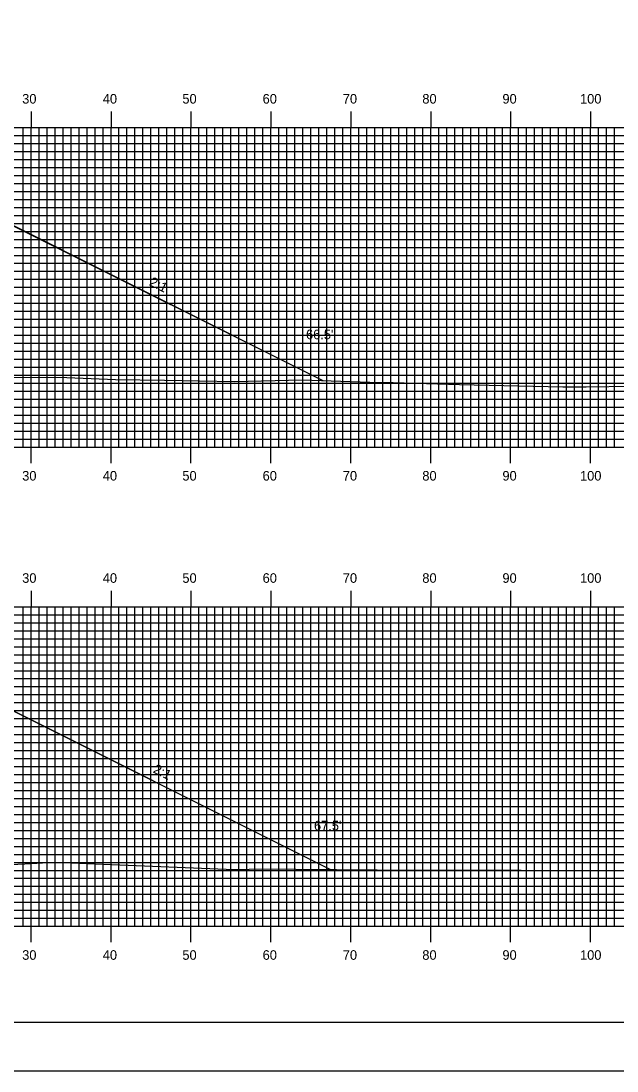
# Model space of a CAD drawing. Extents: x 1810587 to 1810930, y 442591 to 442811.
# Drawn here: x 1810781.1 to 1810855.7, y 442590.5 to 442722 of the extents above; entities that cross this region are included whole.
import ezdxf

# ---------------------------------------------------------------- set-up
doc = ezdxf.new("R2010")
doc.units = 0
for name, color, linetype in [('ANNOTATION', 7, 'Continuous'), ('BORDER', 7, 'Continuous'), ('D_Roadway_Centerline', 7, 'Continuous'), ('D_Roadway_SlopeLines', 7, 'Continuous'), ('D_Text_Standard', 7, 'Continuous'), ('H_V ANNOTATION', 7, 'Continuous'), ('MAJOR', 7, 'Continuous'), ('MINOR', 7, 'Continuous'), ('PLOT BOUNDARY', 7, 'Continuous'), ('S_Roadway_Centerline', 7, 'Continuous')]:
    doc.layers.add(name, color=color, linetype=linetype)

msp = doc.modelspace()

# ---------------------------------------------------------------- linework, layer by layer
at = {"layer": 'BORDER'}
msp.add_lwpolyline([(1810602.78, 442596.67), (1810922.78, 442596.67), (1810922.78, 442806.67), (1810602.78, 442806.67)], close=True, dxfattribs=at)
at = {"layer": 'D_Roadway_Centerline'}
for points in [[(1810685.73, 442678.41), (1810724.17, 442697.62), (1810729.38, 442700.23), (1810732.38, 442700.29), (1810740.38, 442700.45), (1810752.38, 442699.87), (1810764.38, 442699.29), (1810772.38, 442698.91), (1810775.38, 442698.77), (1810780.91, 442696), (1810818.89, 442677.01)], [(1810686.18, 442617.88), (1810724.17, 442636.87), (1810729.38, 442639.48), (1810732.38, 442639.54), (1810740.38, 442639.7), (1810752.38, 442639.12), (1810764.38, 442638.54), (1810772.38, 442638.16), (1810775.38, 442638.02), (1810780.91, 442635.25), (1810819.86, 442615.77)]]:
    msp.add_lwpolyline(points, dxfattribs=at)
at = {"layer": 'D_Roadway_SlopeLines'}
for points in [[(1810775.38, 442698.77), (1810818.89, 442677.01)], [(1810775.38, 442638.02), (1810819.86, 442615.77)]]:
    msp.add_lwpolyline(points, dxfattribs=at)
at = {"layer": 'MAJOR'}
for p, q in [((1810782.38, 442710.67), (1810782.38, 442708.67)), ((1810792.38, 442710.67), (1810792.38, 442708.67)), ((1810802.38, 442710.67), (1810802.38, 442708.67)), ((1810812.38, 442710.67), (1810812.38, 442708.67)), ((1810822.38, 442710.67), (1810822.38, 442708.67)), ((1810832.38, 442710.67), (1810832.38, 442708.67)), ((1810842.38, 442710.67), (1810842.38, 442708.67)), ((1810852.38, 442710.67), (1810852.38, 442708.67)), ((1810612.38, 442708.67), (1810892.38, 442708.67)), ((1810612.38, 442708.67), (1810892.38, 442708.67)), ((1810782.38, 442668.67), (1810782.38, 442708.67)), ((1810792.38, 442668.67), (1810792.38, 442708.67)), ((1810802.38, 442668.67), (1810802.38, 442708.67)), ((1810812.38, 442668.67), (1810812.38, 442708.67)), ((1810822.38, 442668.67), (1810822.38, 442708.67)), ((1810832.38, 442668.67), (1810832.38, 442708.67)), ((1810842.38, 442668.67), (1810842.38, 442708.67)), ((1810852.38, 442668.67), (1810852.38, 442708.67)), ((1810612.38, 442703.67), (1810892.38, 442703.67)), ((1810612.38, 442698.67), (1810892.38, 442698.67)), ((1810612.38, 442693.67), (1810892.38, 442693.67)), ((1810612.38, 442688.67), (1810892.38, 442688.67)), ((1810612.38, 442683.67), (1810892.38, 442683.67)), ((1810612.38, 442678.67), (1810892.38, 442678.67)), ((1810612.38, 442673.67), (1810892.38, 442673.67)), ((1810612.38, 442668.67), (1810892.38, 442668.67)), ((1810612.38, 442668.67), (1810892.38, 442668.67)), ((1810782.38, 442666.66), (1810782.38, 442668.67)), ((1810792.38, 442666.66), (1810792.38, 442668.67)), ((1810802.38, 442666.66), (1810802.38, 442668.67)), ((1810812.38, 442666.66), (1810812.38, 442668.67)), ((1810822.38, 442666.66), (1810822.38, 442668.67)), ((1810832.38, 442666.66), (1810832.38, 442668.67)), ((1810842.38, 442666.66), (1810842.38, 442668.67)), ((1810852.38, 442666.66), (1810852.38, 442668.67)), ((1810782.38, 442650.67), (1810782.38, 442648.67)), ((1810792.38, 442650.67), (1810792.38, 442648.67)), ((1810802.38, 442650.67), (1810802.38, 442648.67)), ((1810812.38, 442650.67), (1810812.38, 442648.67)), ((1810822.38, 442650.67), (1810822.38, 442648.67)), ((1810832.38, 442650.67), (1810832.38, 442648.67)), ((1810842.38, 442650.67), (1810842.38, 442648.67)), ((1810852.38, 442650.67), (1810852.38, 442648.67)), ((1810612.38, 442648.67), (1810892.38, 442648.67)), ((1810612.38, 442648.67), (1810892.38, 442648.67)), ((1810782.38, 442608.67), (1810782.38, 442648.67)), ((1810792.38, 442608.67), (1810792.38, 442648.67)), ((1810802.38, 442608.67), (1810802.38, 442648.67)), ((1810812.38, 442608.67), (1810812.38, 442648.67)), ((1810822.38, 442608.67), (1810822.38, 442648.67)), ((1810832.38, 442608.67), (1810832.38, 442648.67)), ((1810842.38, 442608.67), (1810842.38, 442648.67)), ((1810852.38, 442608.67), (1810852.38, 442648.67)), ((1810612.38, 442643.67), (1810892.38, 442643.67)), ((1810612.38, 442638.67), (1810892.38, 442638.67)), ((1810612.38, 442633.67), (1810892.38, 442633.67)), ((1810612.38, 442628.67), (1810892.38, 442628.67)), ((1810612.38, 442623.67), (1810892.38, 442623.67)), ((1810612.38, 442618.67), (1810892.38, 442618.67)), ((1810612.38, 442613.67), (1810892.38, 442613.67)), ((1810612.38, 442608.67), (1810892.38, 442608.67)), ((1810612.38, 442608.67), (1810892.38, 442608.67)), ((1810782.38, 442606.66), (1810782.38, 442608.67)), ((1810792.38, 442606.66), (1810792.38, 442608.67)), ((1810802.38, 442606.66), (1810802.38, 442608.67)), ((1810812.38, 442606.66), (1810812.38, 442608.67)), ((1810822.38, 442606.66), (1810822.38, 442608.67)), ((1810832.38, 442606.66), (1810832.38, 442608.67)), ((1810842.38, 442606.66), (1810842.38, 442608.67)), ((1810852.38, 442606.66), (1810852.38, 442608.67))]:
    msp.add_line(p, q, dxfattribs=at)
at = {"layer": 'MINOR'}
for p, q in [((1810781.38, 442668.67), (1810781.38, 442708.67)), ((1810783.38, 442668.67), (1810783.38, 442708.67)), ((1810784.38, 442668.67), (1810784.38, 442708.67)), ((1810785.38, 442668.67), (1810785.38, 442708.67)), ((1810786.38, 442668.67), (1810786.38, 442708.67)), ((1810787.38, 442668.67), (1810787.38, 442708.67)), ((1810788.38, 442668.67), (1810788.38, 442708.67)), ((1810789.38, 442668.67), (1810789.38, 442708.67)), ((1810790.38, 442668.67), (1810790.38, 442708.67)), ((1810791.38, 442668.67), (1810791.38, 442708.67)), ((1810793.38, 442668.67), (1810793.38, 442708.67)), ((1810794.38, 442668.67), (1810794.38, 442708.67)), ((1810795.38, 442668.67), (1810795.38, 442708.67)), ((1810796.38, 442668.67), (1810796.38, 442708.67)), ((1810797.38, 442668.67), (1810797.38, 442708.67)), ((1810798.38, 442668.67), (1810798.38, 442708.67)), ((1810799.38, 442668.67), (1810799.38, 442708.67)), ((1810800.38, 442668.67), (1810800.38, 442708.67)), ((1810801.38, 442668.67), (1810801.38, 442708.67)), ((1810803.38, 442668.67), (1810803.38, 442708.67)), ((1810804.38, 442668.67), (1810804.38, 442708.67)), ((1810805.38, 442668.67), (1810805.38, 442708.67)), ((1810806.38, 442668.67), (1810806.38, 442708.67)), ((1810807.38, 442668.67), (1810807.38, 442708.67)), ((1810808.38, 442668.67), (1810808.38, 442708.67)), ((1810809.38, 442668.67), (1810809.38, 442708.67)), ((1810810.38, 442668.67), (1810810.38, 442708.67)), ((1810811.38, 442668.67), (1810811.38, 442708.67)), ((1810813.38, 442668.67), (1810813.38, 442708.67)), ((1810814.38, 442668.67), (1810814.38, 442708.67)), ((1810815.38, 442668.67), (1810815.38, 442708.67)), ((1810816.38, 442668.67), (1810816.38, 442708.67)), ((1810817.38, 442668.67), (1810817.38, 442708.67)), ((1810818.38, 442668.67), (1810818.38, 442708.67)), ((1810819.38, 442668.67), (1810819.38, 442708.67)), ((1810820.38, 442668.67), (1810820.38, 442708.67)), ((1810821.38, 442668.67), (1810821.38, 442708.67)), ((1810823.38, 442668.67), (1810823.38, 442708.67)), ((1810824.38, 442668.67), (1810824.38, 442708.67)), ((1810825.38, 442668.67), (1810825.38, 442708.67)), ((1810826.38, 442668.67), (1810826.38, 442708.67)), ((1810827.38, 442668.67), (1810827.38, 442708.67)), ((1810828.38, 442668.67), (1810828.38, 442708.67)), ((1810829.38, 442668.67), (1810829.38, 442708.67)), ((1810830.38, 442668.67), (1810830.38, 442708.67)), ((1810831.38, 442668.67), (1810831.38, 442708.67)), ((1810833.38, 442668.67), (1810833.38, 442708.67)), ((1810834.38, 442668.67), (1810834.38, 442708.67)), ((1810835.38, 442668.67), (1810835.38, 442708.67)), ((1810836.38, 442668.67), (1810836.38, 442708.67)), ((1810837.38, 442668.67), (1810837.38, 442708.67)), ((1810838.38, 442668.67), (1810838.38, 442708.67)), ((1810839.38, 442668.67), (1810839.38, 442708.67)), ((1810840.38, 442668.67), (1810840.38, 442708.67)), ((1810841.38, 442668.67), (1810841.38, 442708.67)), ((1810843.38, 442668.67), (1810843.38, 442708.67)), ((1810844.38, 442668.67), (1810844.38, 442708.67)), ((1810845.38, 442668.67), (1810845.38, 442708.67)), ((1810846.38, 442668.67), (1810846.38, 442708.67)), ((1810847.38, 442668.67), (1810847.38, 442708.67)), ((1810848.38, 442668.67), (1810848.38, 442708.67)), ((1810849.38, 442668.67), (1810849.38, 442708.67)), ((1810850.38, 442668.67), (1810850.38, 442708.67)), ((1810851.38, 442668.67), (1810851.38, 442708.67)), ((1810853.38, 442668.67), (1810853.38, 442708.67)), ((1810854.38, 442668.67), (1810854.38, 442708.67)), ((1810855.38, 442668.67), (1810855.38, 442708.67)), ((1810612.38, 442707.67), (1810892.38, 442707.67)), ((1810612.38, 442706.67), (1810892.38, 442706.67)), ((1810612.38, 442705.67), (1810892.38, 442705.67)), ((1810612.38, 442704.67), (1810892.38, 442704.67)), ((1810612.38, 442702.67), (1810892.38, 442702.67)), ((1810612.38, 442701.67), (1810892.38, 442701.67)), ((1810612.38, 442700.67), (1810892.38, 442700.67)), ((1810612.38, 442699.67), (1810892.38, 442699.67)), ((1810612.38, 442697.67), (1810892.38, 442697.67)), ((1810612.38, 442696.67), (1810892.38, 442696.67)), ((1810612.38, 442695.67), (1810892.38, 442695.67)), ((1810612.38, 442694.67), (1810892.38, 442694.67)), ((1810612.38, 442692.67), (1810892.38, 442692.67)), ((1810612.38, 442691.67), (1810892.38, 442691.67)), ((1810612.38, 442690.67), (1810892.38, 442690.67)), ((1810612.38, 442689.67), (1810892.38, 442689.67)), ((1810612.38, 442687.67), (1810892.38, 442687.67)), ((1810612.38, 442686.67), (1810892.38, 442686.67)), ((1810612.38, 442685.67), (1810892.38, 442685.67)), ((1810612.38, 442684.67), (1810892.38, 442684.67)), ((1810612.38, 442682.67), (1810892.38, 442682.67)), ((1810612.38, 442681.67), (1810892.38, 442681.67)), ((1810612.38, 442680.67), (1810892.38, 442680.67)), ((1810612.38, 442679.67), (1810892.38, 442679.67)), ((1810612.38, 442677.67), (1810892.38, 442677.67)), ((1810612.38, 442676.67), (1810892.38, 442676.67)), ((1810612.38, 442675.67), (1810892.38, 442675.67)), ((1810612.38, 442674.67), (1810892.38, 442674.67)), ((1810612.38, 442672.67), (1810892.38, 442672.67)), ((1810612.38, 442671.67), (1810892.38, 442671.67)), ((1810612.38, 442670.67), (1810892.38, 442670.67)), ((1810612.38, 442669.67), (1810892.38, 442669.67)), ((1810612.38, 442647.67), (1810892.38, 442647.67)), ((1810781.38, 442608.67), (1810781.38, 442648.67)), ((1810783.38, 442608.67), (1810783.38, 442648.67)), ((1810784.38, 442608.67), (1810784.38, 442648.67)), ((1810785.38, 442608.67), (1810785.38, 442648.67)), ((1810786.38, 442608.67), (1810786.38, 442648.67)), ((1810787.38, 442608.67), (1810787.38, 442648.67)), ((1810788.38, 442608.67), (1810788.38, 442648.67)), ((1810789.38, 442608.67), (1810789.38, 442648.67)), ((1810790.38, 442608.67), (1810790.38, 442648.67)), ((1810791.38, 442608.67), (1810791.38, 442648.67)), ((1810793.38, 442608.67), (1810793.38, 442648.67)), ((1810794.38, 442608.67), (1810794.38, 442648.67)), ((1810795.38, 442608.67), (1810795.38, 442648.67)), ((1810796.38, 442608.67), (1810796.38, 442648.67)), ((1810797.38, 442608.67), (1810797.38, 442648.67)), ((1810798.38, 442608.67), (1810798.38, 442648.67)), ((1810799.38, 442608.67), (1810799.38, 442648.67)), ((1810800.38, 442608.67), (1810800.38, 442648.67)), ((1810801.38, 442608.67), (1810801.38, 442648.67)), ((1810803.38, 442608.67), (1810803.38, 442648.67)), ((1810804.38, 442608.67), (1810804.38, 442648.67)), ((1810805.38, 442608.67), (1810805.38, 442648.67)), ((1810806.38, 442608.67), (1810806.38, 442648.67)), ((1810807.38, 442608.67), (1810807.38, 442648.67)), ((1810808.38, 442608.67), (1810808.38, 442648.67)), ((1810809.38, 442608.67), (1810809.38, 442648.67)), ((1810810.38, 442608.67), (1810810.38, 442648.67)), ((1810811.38, 442608.67), (1810811.38, 442648.67)), ((1810813.38, 442608.67), (1810813.38, 442648.67)), ((1810814.38, 442608.67), (1810814.38, 442648.67)), ((1810815.38, 442608.67), (1810815.38, 442648.67)), ((1810816.38, 442608.67), (1810816.38, 442648.67)), ((1810817.38, 442608.67), (1810817.38, 442648.67)), ((1810818.38, 442608.67), (1810818.38, 442648.67)), ((1810819.38, 442608.67), (1810819.38, 442648.67)), ((1810820.38, 442608.67), (1810820.38, 442648.67)), ((1810821.38, 442608.67), (1810821.38, 442648.67)), ((1810823.38, 442608.67), (1810823.38, 442648.67)), ((1810824.38, 442608.67), (1810824.38, 442648.67)), ((1810825.38, 442608.67), (1810825.38, 442648.67)), ((1810826.38, 442608.67), (1810826.38, 442648.67)), ((1810827.38, 442608.67), (1810827.38, 442648.67)), ((1810828.38, 442608.67), (1810828.38, 442648.67)), ((1810829.38, 442608.67), (1810829.38, 442648.67)), ((1810830.38, 442608.67), (1810830.38, 442648.67)), ((1810831.38, 442608.67), (1810831.38, 442648.67)), ((1810833.38, 442608.67), (1810833.38, 442648.67)), ((1810834.38, 442608.67), (1810834.38, 442648.67)), ((1810835.38, 442608.67), (1810835.38, 442648.67)), ((1810836.38, 442608.67), (1810836.38, 442648.67)), ((1810837.38, 442608.67), (1810837.38, 442648.67)), ((1810838.38, 442608.67), (1810838.38, 442648.67)), ((1810839.38, 442608.67), (1810839.38, 442648.67)), ((1810840.38, 442608.67), (1810840.38, 442648.67)), ((1810841.38, 442608.67), (1810841.38, 442648.67)), ((1810843.38, 442608.67), (1810843.38, 442648.67)), ((1810844.38, 442608.67), (1810844.38, 442648.67)), ((1810845.38, 442608.67), (1810845.38, 442648.67)), ((1810846.38, 442608.67), (1810846.38, 442648.67)), ((1810847.38, 442608.67), (1810847.38, 442648.67)), ((1810848.38, 442608.67), (1810848.38, 442648.67)), ((1810849.38, 442608.67), (1810849.38, 442648.67)), ((1810850.38, 442608.67), (1810850.38, 442648.67)), ((1810851.38, 442608.67), (1810851.38, 442648.67)), ((1810853.38, 442608.67), (1810853.38, 442648.67)), ((1810854.38, 442608.67), (1810854.38, 442648.67)), ((1810855.38, 442608.67), (1810855.38, 442648.67)), ((1810612.38, 442646.67), (1810892.38, 442646.67)), ((1810612.38, 442645.67), (1810892.38, 442645.67)), ((1810612.38, 442644.67), (1810892.38, 442644.67)), ((1810612.38, 442642.67), (1810892.38, 442642.67)), ((1810612.38, 442641.67), (1810892.38, 442641.67)), ((1810612.38, 442640.67), (1810892.38, 442640.67)), ((1810612.38, 442639.67), (1810892.38, 442639.67)), ((1810612.38, 442637.67), (1810892.38, 442637.67)), ((1810612.38, 442636.67), (1810892.38, 442636.67)), ((1810612.38, 442635.67), (1810892.38, 442635.67)), ((1810612.38, 442634.67), (1810892.38, 442634.67)), ((1810612.38, 442632.67), (1810892.38, 442632.67)), ((1810612.38, 442631.67), (1810892.38, 442631.67)), ((1810612.38, 442630.67), (1810892.38, 442630.67)), ((1810612.38, 442629.67), (1810892.38, 442629.67)), ((1810612.38, 442627.67), (1810892.38, 442627.67)), ((1810612.38, 442626.67), (1810892.38, 442626.67)), ((1810612.38, 442625.67), (1810892.38, 442625.67)), ((1810612.38, 442624.67), (1810892.38, 442624.67)), ((1810612.38, 442622.67), (1810892.38, 442622.67)), ((1810612.38, 442621.67), (1810892.38, 442621.67)), ((1810612.38, 442620.67), (1810892.38, 442620.67)), ((1810612.38, 442619.67), (1810892.38, 442619.67)), ((1810612.38, 442617.67), (1810892.38, 442617.67)), ((1810612.38, 442616.67), (1810892.38, 442616.67)), ((1810612.38, 442615.67), (1810892.38, 442615.67)), ((1810612.38, 442614.67), (1810892.38, 442614.67)), ((1810612.38, 442612.67), (1810892.38, 442612.67)), ((1810612.38, 442611.67), (1810892.38, 442611.67)), ((1810612.38, 442610.67), (1810892.38, 442610.67)), ((1810612.38, 442609.67), (1810892.38, 442609.67))]:
    msp.add_line(p, q, dxfattribs=at)
at = {"layer": 'PLOT BOUNDARY'}
msp.add_lwpolyline([(1810586.59, 442590.55), (1810926.59, 442590.55), (1810926.59, 442810.55), (1810586.59, 442810.55)], close=True, dxfattribs=at)
at = {"layer": 'S_Roadway_Centerline'}
for points in [[(1810773.84, 442677.41), (1810786.87, 442677.39), (1810792.95, 442677.14), (1810799.06, 442677.04), (1810807.83, 442676.89), (1810816.29, 442677.09), (1810825.96, 442676.77), (1810827.68, 442676.77), (1810835.99, 442676.51), (1810848.92, 442676.2), (1810851.83, 442676.2), (1810863.27, 442676.36), (1810870.27, 442676.41), (1810877.89, 442676.63), (1810886.2, 442677.02), (1810891.25, 442677.01), (1810892.38, 442677)], [(1810772.76, 442616.06), (1810781.61, 442616.48), (1810785.29, 442616.7), (1810806.8, 442615.83), (1810808.92, 442615.77), (1810810.42, 442615.87), (1810825.7, 442615.72), (1810833.52, 442615.71), (1810834.39, 442615.74), (1810853.03, 442615.66), (1810855.83, 442615.63), (1810858.8, 442615.66), (1810873.76, 442615.88), (1810882.83, 442616.05), (1810889.73, 442616.13), (1810892.38, 442616.25)]]:
    msp.add_lwpolyline(points, dxfattribs=at)

# ---------------------------------------------------------------- texts
at = {"layer": 'ANNOTATION'}
for p in [(1810797.07, 442688.96), (1810797.55, 442627.96)]:
    msp.add_text('2:1', height=1.2, rotation=333.4349, dxfattribs=at).set_placement(p)
at = {"layer": 'D_Text_Standard'}
for s, p in [("66.5'", (1810816.78, 442682.17)), ("67.5'", (1810817.78, 442620.67))]:
    msp.add_text(s, height=1.2, dxfattribs=at).set_placement(p)
at = {"layer": 'H_V ANNOTATION'}
for s, p in [('30', (1810781.27, 442711.67)), ('40', (1810791.35, 442711.67)), ('50', (1810801.31, 442711.67)), ('60', (1810811.35, 442711.67)), ('70', (1810821.38, 442711.67)), ('80', (1810831.33, 442711.67)), ('90', (1810841.35, 442711.67)), ('100', (1810851.06, 442711.67)), ('30', (1810781.27, 442664.47)), ('40', (1810791.35, 442664.47)), ('50', (1810801.31, 442664.47)), ('60', (1810811.35, 442664.47)), ('70', (1810821.38, 442664.47)), ('80', (1810831.33, 442664.47)), ('90', (1810841.35, 442664.47)), ('100', (1810851.06, 442664.47)), ('30', (1810781.27, 442651.67)), ('40', (1810791.35, 442651.67)), ('50', (1810801.31, 442651.67)), ('60', (1810811.35, 442651.67)), ('70', (1810821.38, 442651.67)), ('80', (1810831.33, 442651.67)), ('90', (1810841.35, 442651.67)), ('100', (1810851.06, 442651.67)), ('30', (1810781.27, 442604.47)), ('40', (1810791.35, 442604.47)), ('50', (1810801.31, 442604.47)), ('60', (1810811.35, 442604.47)), ('70', (1810821.38, 442604.47)), ('80', (1810831.33, 442604.47)), ('90', (1810841.35, 442604.47)), ('100', (1810851.06, 442604.47))]:
    msp.add_text(s, height=1.2, dxfattribs=at).set_placement(p)

doc.saveas('drawing.dxf')
